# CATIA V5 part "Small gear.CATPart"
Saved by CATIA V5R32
Part number: Part3
Bounding box of the stored display mesh (mm): x -20 to 20, y -20 to 20, z 0 to 10
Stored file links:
  D:\PROJECTS\Project 2022\CATIA V5 6R 2022\Resources\Part Files\c16_catia_v5_6r2022_prt\Gear Joint-(16-53)\Small gear.CATPart
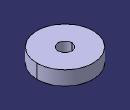
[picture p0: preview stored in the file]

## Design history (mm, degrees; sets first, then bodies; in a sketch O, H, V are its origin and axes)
Body1 (main body)
  Sketch1 on xy-plane, origin (0, 0, 0), H (1, 0, 0), V (0, 1, 0)
    circle A1 centre (0, 0) radius 20
    circle A2 centre (0, 0) radius 5
    radius A1 = 20
    radius A2 = 5
  Pad1: profile Sketch1, direction (0, 0, 1), length 10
